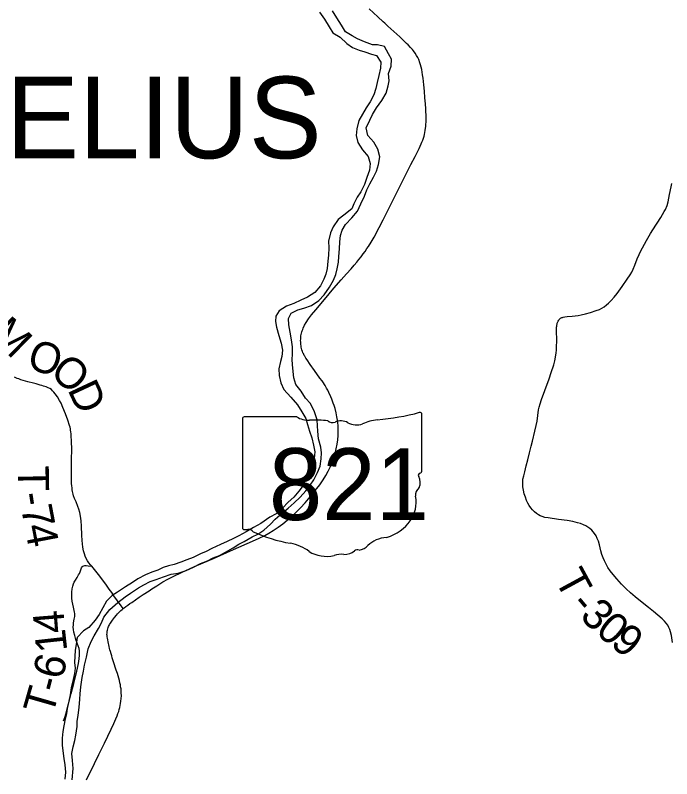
# Model space of a CAD drawing. Extents: x -10.5 to 40.6, y -3.2 to 22.
# Drawn here: x -9.719 to -8.513, y 16.355 to 17.758 of the extents above; entities that cross this region are included whole.
import ezdxf

# ---------------------------------------------------------------- set-up
doc = ezdxf.new("R2010")
doc.units = 0
for name, color, linetype in [('GM_X_Major_River', 7, 'Continuous'), ('GM_X_State_Location', 7, 'Continuous'), ('GM_X_State_Route', 7, 'Continuous'), ('GM_X_State_Shield', 7, 'Continuous'), ('GM_X_Township_Road', 7, 'Continuous'), ('GM_X_Township_Road_Text', 7, 'Continuous'), ('GM_X_Township_Text', 7, 'Continuous')]:
    doc.layers.add(name, color=color, linetype=linetype)

msp = doc.modelspace()

# ---------------------------------------------------------------- linework, layer by layer
at = {"layer": 'GM_X_Major_River'}
for points in [[(-9.3659, 16.7555), (-9.3554, 16.761), (-9.3441, 16.7653), (-9.3328, 16.7715), (-9.3189, 16.7797), (-9.3087, 16.7863), (-9.2985, 16.7914), (-9.2842, 16.7995), (-9.2733, 16.8046), (-9.2624, 16.8119), (-9.2504, 16.8227), (-9.2415, 16.8323), (-9.2287, 16.8431), (-9.2179, 16.8524), (-9.207, 16.862), (-9.1958, 16.8724), (-9.1853, 16.8843), (-9.1771, 16.8946), (-9.1704, 16.9042), (-9.1638, 16.9176), (-9.159, 16.9298), (-9.1569, 16.9427), (-9.1567, 16.9537), (-9.158, 16.9643), (-9.1623, 16.9794), (-9.1633, 16.9938), (-9.1638, 17.0037), (-9.1643, 17.0147), (-9.1695, 17.0294), (-9.1765, 17.0445), (-9.1857, 17.0542), (-9.1939, 17.067), (-9.2035, 17.0797), (-9.2075, 17.0918), (-9.2088, 17.1032), (-9.2101, 17.1161), (-9.2106, 17.1255), (-9.21, 17.135), (-9.2101, 17.1487), (-9.2115, 17.1616), (-9.2139, 17.1756), (-9.2168, 17.1888), (-9.2173, 17.2005), (-9.2121, 17.2105), (-9.2001, 17.2167), (-9.1891, 17.2199), (-9.1752, 17.2246), (-9.1613, 17.2339), (-9.1515, 17.2439), (-9.1419, 17.2585), (-9.1345, 17.2711), (-9.1301, 17.2817), (-9.1275, 17.292), (-9.1254, 17.3042), (-9.1244, 17.3148), (-9.1235, 17.3285), (-9.1229, 17.3414), (-9.1216, 17.3532), (-9.1187, 17.3627), (-9.1127, 17.3734), (-9.1011, 17.3857), (-9.0907, 17.398), (-9.0841, 17.4113), (-9.0774, 17.4251), (-9.073, 17.4373), (-9.0679, 17.4479), (-9.0612, 17.4602), (-9.0557, 17.4712), (-9.0521, 17.4838), (-9.0492, 17.4979), (-9.0532, 17.5119), (-9.0602, 17.5243), (-9.0717, 17.537), (-9.0742, 17.5506), (-9.0679, 17.5648), (-9.0628, 17.5754), (-9.0557, 17.5877), (-9.0457, 17.6011), (-9.0375, 17.6148), (-9.0343, 17.6278), (-9.0325, 17.6373), (-9.0335, 17.6509), (-9.0283, 17.6639), (-9.0278, 17.6768), (-9.0332, 17.687), (-9.0406, 17.7001), (-9.0535, 17.7034), (-9.063, 17.7032), (-9.0775, 17.7087), (-9.0905, 17.7146), (-9.1004, 17.7198), (-9.1126, 17.7272), (-9.12, 17.7393), (-9.1281, 17.7528), (-9.1363, 17.7656)], [(-9.1605, 17.7634), (-9.1512, 17.7506), (-9.1427, 17.7363), (-9.1357, 17.7254), (-9.1223, 17.7176), (-9.1097, 17.706), (-9.0997, 17.6986), (-9.0871, 17.6934), (-9.0772, 17.6902), (-9.0647, 17.6862), (-9.0552, 17.6836), (-9.0478, 17.6716), (-9.0484, 17.6602), (-9.0509, 17.6469), (-9.0545, 17.6343), (-9.0566, 17.6233), (-9.0606, 17.6115), (-9.0669, 17.5989), (-9.0743, 17.5878), (-9.0814, 17.5759), (-9.0877, 17.5641), (-9.0916, 17.5489), (-9.093, 17.5367), (-9.0898, 17.5239), (-9.0812, 17.5107), (-9.0708, 17.4983), (-9.0669, 17.4851), (-9.0686, 17.4733), (-9.073, 17.4596), (-9.0773, 17.4467), (-9.084, 17.4333), (-9.0911, 17.4237), (-9.0969, 17.4115), (-9.101, 17.402), (-9.1156, 17.3904), (-9.1257, 17.3827), (-9.1354, 17.3689), (-9.1402, 17.3578), (-9.1434, 17.343), (-9.1432, 17.3305), (-9.1438, 17.3172), (-9.1448, 17.3058), (-9.1461, 17.2925), (-9.1486, 17.2823), (-9.1523, 17.2727), (-9.1586, 17.2609), (-9.169, 17.2482), (-9.1822, 17.2401), (-9.1946, 17.2346), (-9.2071, 17.228), (-9.221, 17.2232), (-9.2345, 17.2147), (-9.2405, 17.2048), (-9.2411, 17.1949), (-9.2394, 17.1847), (-9.2347, 17.1692), (-9.2307, 17.1556), (-9.2283, 17.1424), (-9.2296, 17.131), (-9.2321, 17.1215), (-9.235, 17.1085), (-9.2344, 17.096), (-9.2312, 17.0824), (-9.2258, 17.07), (-9.2131, 17.0565), (-9.2007, 17.0419), (-9.1926, 17.0295), (-9.1852, 17.017), (-9.1824, 17.0061), (-9.1788, 16.994), (-9.1741, 16.9815), (-9.1713, 16.9679), (-9.1685, 16.9558), (-9.1702, 16.9433), (-9.1757, 16.9307), (-9.182, 16.9166), (-9.1878, 16.9013), (-9.1922, 16.8918), (-9.1983, 16.8834), (-9.2071, 16.8724), (-9.2181, 16.8633), (-9.2283, 16.8523), (-9.2397, 16.8422), (-9.2518, 16.8356), (-9.2679, 16.8244), (-9.2818, 16.8166), (-9.295, 16.8092), (-9.3082, 16.8015), (-9.318, 16.7964), (-9.3296, 16.7913), (-9.3424, 16.7854), (-9.3583, 16.778), (-9.3684, 16.773), (-9.379, 16.7686), (-9.3926, 16.762)], [(-9.3926, 16.762), (-9.4042, 16.7577), (-9.4148, 16.753), (-9.4272, 16.7486), (-9.4375, 16.7466), (-9.4476, 16.7431), (-9.4574, 16.7384), (-9.4684, 16.7348), (-9.4797, 16.7301), (-9.494, 16.7227), (-9.5041, 16.7161), (-9.5165, 16.7076), (-9.5316, 16.6979), (-9.5414, 16.6921), (-9.5518, 16.6813), (-9.5585, 16.6691), (-9.5651, 16.6569), (-9.5722, 16.6469), (-9.5842, 16.6335), (-9.5939, 16.6273), (-9.6055, 16.6146), (-9.6076, 16.6017), (-9.609, 16.5914), (-9.6102, 16.5687), (-9.6093, 16.5584), (-9.6103, 16.5486), (-9.6128, 16.5375), (-9.6164, 16.5223), (-9.6181, 16.5098), (-9.621, 16.4976), (-9.6238, 16.4843), (-9.6252, 16.4748), (-9.6274, 16.4653), (-9.6302, 16.4527), (-9.6316, 16.4421), (-9.633, 16.4299), (-9.6328, 16.4163), (-9.6298, 16.3924), (-9.6285, 16.3811), (-9.6268, 16.3678), (-9.6285, 16.3545)], [(-9.6149, 16.3535), (-9.6129, 16.3741), (-9.6142, 16.3888), (-9.6155, 16.4017), (-9.6126, 16.4139), (-9.6098, 16.4257), (-9.608, 16.4352), (-9.6056, 16.4512), (-9.6053, 16.4606), (-9.604, 16.4724), (-9.6019, 16.4865), (-9.6009, 16.5017), (-9.6003, 16.5115), (-9.5986, 16.5244), (-9.5962, 16.5415), (-9.5937, 16.5533), (-9.5919, 16.564), (-9.5883, 16.5788), (-9.5855, 16.594), (-9.58, 16.6074), (-9.5741, 16.6181), (-9.5663, 16.6311), (-9.5611, 16.6418), (-9.5567, 16.6521), (-9.5456, 16.6663), (-9.5309, 16.6794), (-9.5174, 16.6894), (-9.5077, 16.6964), (-9.493, 16.706), (-9.4832, 16.7115), (-9.4712, 16.7177), (-9.4606, 16.7216), (-9.4467, 16.726), (-9.4327, 16.7311), (-9.4198, 16.7332), (-9.4055, 16.7379), (-9.3919, 16.7442), (-9.3787, 16.7508), (-9.3659, 16.7555)]]:
    msp.add_lwpolyline(points, dxfattribs=at)
at = {"layer": 'GM_X_State_Route'}
for points in [[(-9.035, 17.7382), (-9.0385, 17.7413), (-9.0403, 17.743), (-9.043, 17.7455), (-9.0531, 17.7547), (-9.0689, 17.7696)], [(-9.5881, 16.3535), (-9.5738, 16.3832), (-9.5655, 16.3999), (-9.5553, 16.4205), (-9.5429, 16.4462), (-9.538, 16.457), (-9.5361, 16.4614), (-9.5343, 16.4657), (-9.5321, 16.4709), (-9.5305, 16.4751), (-9.5292, 16.479), (-9.5282, 16.4826), (-9.5271, 16.4865), (-9.5263, 16.4899), (-9.5256, 16.4937), (-9.525, 16.4977), (-9.5244, 16.503), (-9.5243, 16.508), (-9.5244, 16.513), (-9.5245, 16.5164), (-9.5249, 16.5203), (-9.5256, 16.5243), (-9.5262, 16.5282), (-9.527, 16.5318), (-9.528, 16.5359), (-9.5291, 16.5403), (-9.5303, 16.5442), (-9.5317, 16.5489), (-9.5336, 16.5548), (-9.535, 16.5588), (-9.5376, 16.5665), (-9.5388, 16.5703), (-9.5399, 16.5738), (-9.541, 16.5775), (-9.5421, 16.581), (-9.5432, 16.5847), (-9.5444, 16.589), (-9.5452, 16.5921), (-9.5459, 16.5949), (-9.5468, 16.5984), (-9.5475, 16.6015), (-9.5481, 16.6041), (-9.5487, 16.6068), (-9.5494, 16.6105), (-9.55, 16.6136), (-9.5504, 16.6161), (-9.5506, 16.6185), (-9.5508, 16.6205), (-9.5507, 16.6226), (-9.5506, 16.6246), (-9.5503, 16.6264), (-9.55, 16.6284), (-9.5493, 16.6309), (-9.5487, 16.633), (-9.5479, 16.6351), (-9.547, 16.6369), (-9.546, 16.6386), (-9.5445, 16.6411), (-9.5431, 16.6432), (-9.5406, 16.6468), (-9.5369, 16.6516), (-9.5333, 16.656), (-9.5315, 16.658), (-9.5296, 16.6601), (-9.5273, 16.6623), (-9.5253, 16.6643), (-9.523, 16.6661), (-9.521, 16.6678), (-9.5189, 16.6695), (-9.5158, 16.6718), (-9.5124, 16.6744), (-9.5087, 16.677), (-9.5053, 16.6794), (-9.4986, 16.6839), (-9.4914, 16.6888), (-9.4842, 16.6936), (-9.4734, 16.7008), (-9.4682, 16.7043), (-9.4594, 16.71), (-9.4483, 16.7168), (-9.4392, 16.722), (-9.4281, 16.7276), (-9.4136, 16.7345), (-9.3897, 16.7451), (-9.355, 16.7602), (-9.3185, 16.7762), (-9.2832, 16.7915), (-9.2708, 16.7973), (-9.2608, 16.8024), (-9.2532, 16.8067), (-9.2452, 16.8116), (-9.2364, 16.8175), (-9.2279, 16.8238), (-9.2195, 16.8303), (-9.211, 16.8376), (-9.2028, 16.8453), (-9.1949, 16.8532), (-9.1865, 16.8624), (-9.1772, 16.8733), (-9.1682, 16.8845), (-9.1599, 16.8954), (-9.1535, 16.9046), (-9.1485, 16.9125), (-9.1442, 16.9201), (-9.1406, 16.9274), (-9.1373, 16.9349), (-9.1343, 16.9431), (-9.1316, 16.952), (-9.1293, 16.9611), (-9.1276, 16.9697), (-9.1265, 16.9777), (-9.1258, 16.9858), (-9.1257, 16.994), (-9.126, 17.0021), (-9.1268, 17.0108), (-9.1282, 17.0201), (-9.1296, 17.0274), (-9.1316, 17.0353), (-9.1333, 17.0407), (-9.1349, 17.0454), (-9.1376, 17.0524), (-9.1396, 17.057), (-9.1432, 17.0649), (-9.1452, 17.0688), (-9.1473, 17.0726), (-9.1501, 17.0774), (-9.1543, 17.0841), (-9.1556, 17.086), (-9.1595, 17.0914), (-9.1693, 17.1049), (-9.1776, 17.1164), (-9.1831, 17.1246), (-9.1852, 17.1281), (-9.1872, 17.1314), (-9.1881, 17.133), (-9.1891, 17.1346), (-9.1899, 17.1362), (-9.1906, 17.1379), (-9.1916, 17.1402), (-9.1925, 17.1429), (-9.1931, 17.1453), (-9.1937, 17.1479), (-9.194, 17.1502), (-9.1943, 17.1528), (-9.1947, 17.1573), (-9.1949, 17.16), (-9.1948, 17.1626), (-9.1946, 17.1659), (-9.1943, 17.1686), (-9.1939, 17.1712), (-9.1933, 17.1737), (-9.1926, 17.1762), (-9.192, 17.1782), (-9.1911, 17.1806), (-9.1903, 17.1828), (-9.1876, 17.1883), (-9.1846, 17.1936), (-9.1805, 17.1998), (-9.175, 17.2073), (-9.1672, 17.2169), (-9.151, 17.2358), (-9.1337, 17.2561), (-9.1204, 17.2717), (-9.1104, 17.283), (-9.102, 17.2919), (-9.0964, 17.2988), (-9.0918, 17.3043), (-9.0877, 17.3093), (-9.0839, 17.3142), (-9.0798, 17.3193), (-9.0765, 17.3239), (-9.073, 17.329), (-9.0701, 17.3332), (-9.0652, 17.3411), (-9.0599, 17.3502), (-9.0506, 17.3678), (-9.0431, 17.3821), (-9.0351, 17.3976), (-9.0093, 17.4492), (-8.9978, 17.4726), (-8.9921, 17.4836), (-8.9846, 17.498), (-8.9772, 17.513), (-8.9732, 17.5215), (-8.9719, 17.5247), (-8.9704, 17.5285), (-8.9693, 17.5319), (-8.9682, 17.5357), (-8.9674, 17.5388), (-8.9667, 17.5424), (-8.966, 17.5459), (-8.9654, 17.55), (-8.9651, 17.5532), (-8.9648, 17.5573), (-8.9645, 17.5614), (-8.9644, 17.5654), (-8.9644, 17.5701), (-8.9645, 17.5748), (-8.9647, 17.5801), (-8.965, 17.586), (-8.9656, 17.595), (-8.9666, 17.6058), (-8.9675, 17.6181), (-8.9688, 17.6299), (-8.9693, 17.6361), (-8.9699, 17.6422), (-8.9707, 17.6485), (-8.9714, 17.6533), (-8.9723, 17.6582), (-8.9732, 17.6624), (-8.9744, 17.6666), (-8.9756, 17.6702), (-8.9778, 17.6761), (-8.9798, 17.6801), (-8.9819, 17.6839), (-8.9847, 17.6881), (-8.9876, 17.6921), (-8.9896, 17.6946), (-8.9912, 17.6965), (-8.9929, 17.6983), (-8.9975, 17.7033), (-9.0002, 17.706), (-9.0052, 17.7106), (-9.0129, 17.7178), (-9.0344, 17.7375), (-9.035, 17.7382)]]:
    msp.add_lwpolyline(points, dxfattribs=at)
at = {"layer": 'GM_X_State_Shield'}
for p, q in [((-8.9722, 16.9203), (-8.9722, 17.025)), ((-9.3018, 17.0166), (-9.3018, 16.8165)), ((-9.202, 17.02), (-9.2986, 17.02)), ((-8.9723, 16.9203), (-8.9722, 16.9203))]:
    msp.add_line(p, q, dxfattribs=at)
for centre, major_axis, start_param, end_param in [((-9.0896, 17.2929), (0.3495, 0), 4.814394, 5.042369), ((-8.9759, 17.0254), (0.00367, 0), 6.141152, 7.989035), ((-9.298, 17.017), (0.00382, 0), 1.712693, 3.28349), ((-9.1791, 17.0433), (0.037, 0), 4.042523, 4.731795), ((-9.1668, 16.9077), (0.133, 0), 1.404758, 1.657858), ((-9.1366, 17.018), (0.0107, 0), 3.836095, 5.185415), ((-9.1209, 16.9949), (0.0222, 0), 0.950623, 2.079405), ((-9.0922, 17.0266), (0.0267, 0), 4.081561, 5.145723), ((-9.045, 16.9589), (0.0703, 0), 1.699011, 2.107814), ((-8.9731, 16.9126), (0.00568, 0), 1.883978, 3.671073), ((-9.0092, 16.8994), (0.0341, 0), 5.934695, 6.695948), ((-8.9761, 16.9199), (0.00393, 0), 5.05454, 6.418171), ((-8.9591, 16.8765), (0.0248, 0), 2.387724, 3.262537), ((-9.07, 16.8632), (0.0874, 0), 5.101752, 6.440018), ((-9.298, 16.816), (0.00385, 0), 3.00124, 4.508301), ((-9.2974, 16.8365), (0.0294, 0), 4.665946, 4.897461), ((-9.2914, 16.8049), (0.0106, 0), 0.519207, 1.627899), ((-9.1576, 16.9847), (0.2524, 0), 4.195997, 4.488961), ((-9.0332, 16.7603), (0.0479, 0), 1.647645, 2.488434), ((-9.2328, 16.7266), (0.079, 0), 0.823519, 1.323587), ((-9.1474, 16.8039), (0.0501, 0), 4.026481, 4.996735), ((-9.1148, 16.7889), (0.0267, 0), 4.691044, 5.507374), ((-9.0906, 16.7696), (0.00752, 0), 1.147584, 2.315152), ((-9.0938, 16.7971), (0.0282, 0), 4.937069, 5.64225), ((-9.1185, 16.7347), (0.0412, 0), 1.495662, 1.94098)]:
    msp.add_ellipse(centre, major_axis=major_axis, ratio=0.8, start_param=start_param, end_param=end_param, dxfattribs=at)
at = {"layer": 'GM_X_Township_Road'}
for points in [[(-8.5117, 16.6057), (-8.5136, 16.6186), (-8.5151, 16.6253), (-8.5164, 16.6294), (-8.5181, 16.6334), (-8.5202, 16.6372), (-8.5231, 16.6413), (-8.5263, 16.645), (-8.5303, 16.6489), (-8.5464, 16.6624), (-8.5555, 16.6699), (-8.5704, 16.6818), (-8.5802, 16.6895), (-8.5887, 16.6968), (-8.5968, 16.7045), (-8.6051, 16.7128), (-8.6138, 16.7225), (-8.6206, 16.7305), (-8.6259, 16.7374), (-8.6301, 16.7435), (-8.6336, 16.7494), (-8.6367, 16.7555), (-8.6392, 16.7612), (-8.6412, 16.7671), (-8.643, 16.7737), (-8.6458, 16.7851), (-8.6478, 16.7916), (-8.6498, 16.7969), (-8.652, 16.8013), (-8.6546, 16.8056), (-8.6572, 16.809), (-8.6601, 16.8122), (-8.6634, 16.8151), (-8.6669, 16.8177), (-8.6707, 16.8199), (-8.6752, 16.822), (-8.6804, 16.824), (-8.6863, 16.8257), (-8.6948, 16.8276), (-8.7052, 16.8295), (-8.7212, 16.8317), (-8.7402, 16.8345), (-8.7463, 16.8355), (-8.7509, 16.8368), (-8.7548, 16.8385), (-8.7579, 16.8403), (-8.7615, 16.8427), (-8.7653, 16.8459), (-8.7689, 16.8493), (-8.7721, 16.8531), (-8.7749, 16.8572), (-8.7774, 16.8615), (-8.7798, 16.8665), (-8.7819, 16.8723), (-8.7839, 16.8788), (-8.7854, 16.8854), (-8.7863, 16.8915), (-8.7867, 16.897), (-8.7868, 16.9012), (-8.7863, 16.9055), (-8.785, 16.912), (-8.7832, 16.9191), (-8.7805, 16.9299), (-8.7775, 16.9413), (-8.7744, 16.9539), (-8.7714, 16.966), (-8.7691, 16.9756), (-8.7645, 16.9936), (-8.762, 17.0039), (-8.7605, 17.0124), (-8.7575, 17.0327), (-8.7565, 17.0376), (-8.7548, 17.0442), (-8.7524, 17.0519), (-8.7463, 17.0682), (-8.7383, 17.0898), (-8.7343, 17.1015), (-8.7298, 17.1157), (-8.7278, 17.1229), (-8.7264, 17.1296), (-8.7253, 17.1376), (-8.7249, 17.1425), (-8.7248, 17.1456), (-8.7246, 17.1499), (-8.7244, 17.1586), (-8.7247, 17.1802), (-8.7246, 17.1829), (-8.7245, 17.1851), (-8.7244, 17.1862), (-8.7243, 17.1873), (-8.724, 17.1888), (-8.7237, 17.1904), (-8.7233, 17.1919), (-8.7228, 17.1934), (-8.7223, 17.1947), (-8.7215, 17.196), (-8.7207, 17.1975), (-8.72, 17.1986), (-8.719, 17.1996), (-8.7182, 17.2005), (-8.7172, 17.2012), (-8.7162, 17.2018), (-8.7151, 17.2024), (-8.7139, 17.2028), (-8.7124, 17.2032), (-8.7093, 17.2038), (-8.705, 17.2043), (-8.6957, 17.2051), (-8.6852, 17.2061), (-8.6791, 17.2072), (-8.6713, 17.209), (-8.6623, 17.2117), (-8.6517, 17.2151), (-8.6459, 17.2174), (-8.6415, 17.2196), (-8.6372, 17.2222), (-8.6327, 17.2256), (-8.629, 17.2288), (-8.6242, 17.2337), (-8.6189, 17.2398), (-8.6135, 17.2466), (-8.604, 17.2597), (-8.5947, 17.2728), (-8.5896, 17.2806), (-8.5865, 17.286), (-8.5838, 17.2916), (-8.581, 17.2984), (-8.5763, 17.3104), (-8.5729, 17.3183), (-8.5714, 17.3216), (-8.567, 17.3304), (-8.5596, 17.3439), (-8.5547, 17.3525), (-8.5517, 17.3571), (-8.5477, 17.3634), (-8.5333, 17.3859), (-8.5266, 17.397), (-8.5244, 17.4008), (-8.5214, 17.4082), (-8.5196, 17.4148), (-8.5168, 17.4282), (-8.5142, 17.4423), (-8.5125, 17.4489)], [(-9.5786, 16.7459), (-9.581, 16.7485), (-9.5838, 16.7518), (-9.5863, 16.7554), (-9.5887, 16.7597), (-9.5908, 16.7642), (-9.5923, 16.7683), (-9.5936, 16.7737), (-9.5949, 16.781), (-9.5963, 16.7927), (-9.5971, 16.8026), (-9.5977, 16.8193), (-9.5984, 16.8292), (-9.5995, 16.8378), (-9.6008, 16.8445), (-9.6024, 16.8505), (-9.6043, 16.8557), (-9.6076, 16.8637), (-9.6103, 16.8699), (-9.6121, 16.8752), (-9.6129, 16.8779), (-9.6135, 16.8806), (-9.6139, 16.8829), (-9.6145, 16.8861), (-9.615, 16.8895), (-9.6154, 16.8935), (-9.6158, 16.8976), (-9.616, 16.9015), (-9.6161, 16.9072), (-9.6162, 16.9133), (-9.6157, 16.9419), (-9.6156, 16.9599), (-9.6158, 16.9754), (-9.6163, 16.9854), (-9.6165, 16.9888), (-9.617, 16.9927), (-9.6175, 16.9956), (-9.618, 16.9983), (-9.6186, 17.0011), (-9.6195, 17.0043), (-9.6226, 17.0137), (-9.6269, 17.0254), (-9.6318, 17.0375), (-9.6351, 17.0449), (-9.6377, 17.0498), (-9.6419, 17.0567), (-9.6457, 17.0623), (-9.6485, 17.0656), (-9.6508, 17.0681), (-9.6529, 17.0701), (-9.6558, 17.072), (-9.659, 17.0736), (-9.6627, 17.0752), (-9.6672, 17.0767), (-9.6706, 17.0777), (-9.6738, 17.0785), (-9.6772, 17.0795), (-9.6807, 17.0804), (-9.6859, 17.0817), (-9.6961, 17.0844), (-9.705, 17.087), (-9.7091, 17.0883), (-9.7127, 17.0896), (-9.7157, 17.0907), (-9.7184, 17.092), (-9.7206, 17.093)], [(-9.6308, 16.4618), (-9.6295, 16.4646), (-9.6282, 16.4681), (-9.6264, 16.4741), (-9.6217, 16.4928), (-9.6164, 16.5119), (-9.6114, 16.5305), (-9.6062, 16.5529), (-9.6033, 16.5669), (-9.6018, 16.5755), (-9.6011, 16.5823), (-9.601, 16.5867), (-9.6013, 16.5904), (-9.602, 16.5946), (-9.6034, 16.5994), (-9.6072, 16.6093), (-9.6086, 16.6134), (-9.6101, 16.6188), (-9.6115, 16.6249), (-9.6122, 16.6298), (-9.6126, 16.6341), (-9.6125, 16.6378), (-9.6121, 16.6415), (-9.6108, 16.6483), (-9.6099, 16.6532), (-9.6098, 16.6563), (-9.6101, 16.6587), (-9.6104, 16.6611), (-9.6121, 16.6703), (-9.6145, 16.6818), (-9.6152, 16.6873), (-9.6154, 16.6923), (-9.6151, 16.6979), (-9.6145, 16.7041), (-9.6135, 16.7089), (-9.6123, 16.7131), (-9.6109, 16.7166), (-9.6089, 16.7204), (-9.6058, 16.7251), (-9.6028, 16.7298), (-9.6014, 16.7326), (-9.6002, 16.7354), (-9.5984, 16.7407), (-9.5974, 16.743), (-9.5963, 16.7445), (-9.5949, 16.7456), (-9.5932, 16.7464), (-9.5914, 16.7468), (-9.5889, 16.747), (-9.5852, 16.7466), (-9.5786, 16.7459)], [(-9.521, 16.6678), (-9.5247, 16.673), (-9.5312, 16.682), (-9.538, 16.6916), (-9.5419, 16.6972), (-9.5465, 16.7038), (-9.5531, 16.7129), (-9.5661, 16.7303), (-9.5786, 16.7459)]]:
    msp.add_lwpolyline(points, dxfattribs=at)

# ---------------------------------------------------------------- texts
at = {"layer": 'GM_X_State_Location'}
for s in ['s', 'r']:
    msp.add_text(s, height=0.000189, dxfattribs=at).set_placement((-9.1407, 16.9032))
msp.add_text('821', height=0.000189, rotation=0, dxfattribs=at).set_placement((-9.2076, 16.8894))
at = {"layer": 'GM_X_State_Shield'}
msp.add_text('821', height=0.13184, dxfattribs=at).set_placement((-9.2532, 16.8306))
at = {"layer": 'GM_X_Township_Road_Text'}
for s, rotation, p in [('M', 315.7458, (-9.7683, 17.1684)), ('O', 341.4323, (-9.7006, 17.111)), ('O', 319.4864, (-9.6581, 17.0979)), ('D', 295.0563, (-9.624, 17.0705)), ('T', 270.9901, (-9.7145, 16.9297)), ('-', 279.2557, (-9.713, 16.8783)), ('7', 280.7533, (-9.709, 16.8537)), ('4', 280.9802, (-9.7024, 16.8191)), ('T', 298.5126, (-8.7292, 16.7218)), ('-', 310.1844, (-8.7018, 16.674)), ('3', 314.2996, (-8.6838, 16.6529)), ('4', 94.6626, (-9.6273, 16.6245)), ('0', 319.8162, (-8.655, 16.6238)), ('9', 321.2792, (-8.6279, 16.601)), ('1', 96.2779, (-9.6235, 16.5904)), ('6', 77.2043, (-9.6324, 16.536)), ('-', 75.2058, (-9.6388, 16.5116)), ('T', 73.9521, (-9.6509, 16.4695))]:
    msp.add_text(s, height=0.0568, rotation=rotation, dxfattribs=at).set_placement(p)
at = {"layer": 'GM_X_Township_Text'}
msp.add_text('AURELIUS', height=0.15, rotation=0, dxfattribs=at).set_placement((-10.1595, 17.4949))

doc.saveas('drawing.dxf')
